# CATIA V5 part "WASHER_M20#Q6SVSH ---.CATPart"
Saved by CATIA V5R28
Part number: WASHER_M20#Q6SVRS
Revision: ---
Nomenclature: _
Description: WASHER_M20
Property "REP": "CM"
Property "PREF": "Y"
Property "PBS 1": "24"
Property "PBS 2": "CR"
Property "PBS 3": "LC"
Property "DEPT": "_"
Property "DIVN": "_"
Property "GROUP": "_"
Property "UNIT": "_"
Property "PARTY": "_"
Property "RO": "---"
Property "RE": "SEKACHI"
Property "PRO": "---"
Property "Change Type": "Major"
Property "Maturity Level": "CD"
Property "Export Number": "_"
Property "Description Modification": "FDRModel"
Property "Description Documents": "_"
Property "BOM": "_"
Property "AT": "PD"
Property "External Part ID": "_"
Property "LONG": "_"
Property "ID": "Q6SVRS"
Property "User In Enovia": "VAUQUEJ"
Property "Object Type": "_"
Property "CADENAS_ID": "_"
Property "Life Cycle Status": "Approved"
Bounding box of the stored display mesh (mm): x -20 to 20, y -19.021 to 19.021, z -2 to 0
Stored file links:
  C:\Users\pandeym\Desktop\__TCPH\WASHER_M20#Q6SVSH ---.CATPart
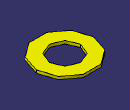
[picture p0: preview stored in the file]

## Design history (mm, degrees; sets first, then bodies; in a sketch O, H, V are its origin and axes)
Body1 (main body)
  Sketch1 on xy-plane, origin (0, 0, 0), H (1, 0, 0), V (0, 1, 0)
    circle A1 centre (0, 0) radius 11
    circle A2 centre (0, 0) radius 20
    point P1 (20, 0)
    radius A1 = 11
    radius A2 = 20
    coincidence: A2 P1, P1 H
  Pad1: profile Sketch1, direction (0, 0, -1), length 2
